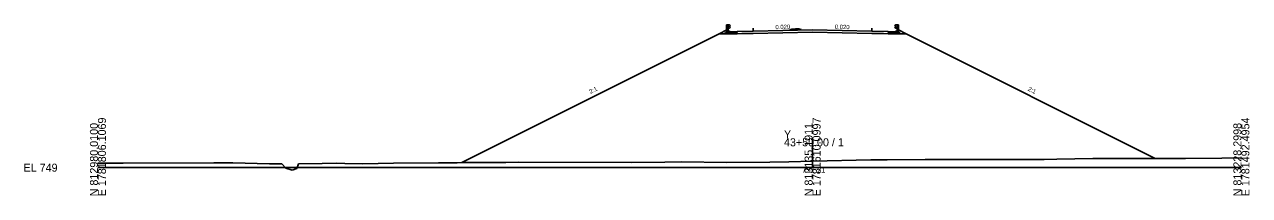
# Model space of a CAD drawing. Extents: x -12583 to 5303, y -44 to 25667.
# Drawn here: x 2874.3 to 3302.8, y 3990.3 to 4049.9 of the extents above; entities that cross this region are included whole.
import ezdxf

# ---------------------------------------------------------------- set-up
doc = ezdxf.new("R2010")
doc.units = 0
for name, color, linetype in [('Exist Cross Section Cell', 7, 'Continuous'), ('Exist XS Center Line Elevation Label', 7, 'Continuous'), ('Exist XS Ground Line', 7, 'Continuous'), ('Prop Conc 5in Monolithic Surface Mount Island', 7, 'Continuous'), ('Prop XS Dump Level', 7, 'Continuous'), ('Prop XS Earthwork Shape', 7, 'Continuous'), ('Prop XS EOT Tick Mark', 7, 'Continuous'), ('Prop XS Finish Grade', 7, 'Continuous'), ('Prop XS Finish Grade CurbGutter', 7, 'Continuous'), ('Prop XS Finish Grade Earthwork', 7, 'Continuous'), ('Prop XS Finish Grade Paved Shoulder', 7, 'Continuous'), ('Prop XS Finish Grade Pavement', 7, 'Continuous'), ('Prop XS Guardrail', 7, 'Continuous'), ('Prop XS Pvmt Edge Slope', 7, 'Continuous'), ('Prop XS SE Text', 7, 'Continuous'), ('Prop XS Side Slope Text', 7, 'Continuous'), ('Prop XS Subgrade CurbGutter', 7, 'Continuous'), ('Prop XS Subgrade Earthwork', 7, 'Continuous')]:
    doc.layers.add(name, color=color, linetype=linetype)

msp = doc.modelspace()

# ---------------------------------------------------------------- linework, layer by layer
at = {"layer": 'Exist Cross Section Cell'}
for p, q in [((3150, 4000), (3150, 4010.25)), ((2900, 4000), (3150, 4000)), ((3150, 4000), (3300, 4000))]:
    msp.add_line(p, q, dxfattribs=at)
at = {"layer": 'Exist XS Ground Line'}
for p, q in [((3150, 4002.21), (3170.43, 4002.73)), ((3170.43, 4002.73), (3176.11, 4002.68)), ((3176.11, 4002.68), (3189.37, 4002.82)), ((3189.37, 4002.82), (3202.3, 4002.89)), ((3202.3, 4002.89), (3221.1, 4002.86)), ((3221.1, 4002.86), (3230.99, 4002.9)), ((3230.99, 4002.9), (3235.46, 4002.98)), ((3235.46, 4002.98), (3248.09, 4003.22)), ((3248.09, 4003.22), (3249.41, 4003.25)), ((3249.41, 4003.25), (3251.28, 4003.24)), ((3251.28, 4003.24), (3267.82, 4003.2)), ((3267.82, 4003.2), (3280.49, 4003.16)), ((3280.49, 4003.16), (3293.13, 4003.35)), ((3293.13, 4003.35), (3300, 4003.42)), ((2900, 4001.53), (2904.75, 4001.58)), ((2904.75, 4001.58), (2908.78, 4001.58)), ((2908.78, 4001.58), (2940.5, 4001.69)), ((2940.5, 4001.69), (2943.57, 4001.65)), ((2943.57, 4001.65), (2944.72, 4001.71)), ((2944.72, 4001.71), (2947.19, 4001.66)), ((2947.19, 4001.66), (2960.04, 4001.36)), ((2960.04, 4001.36), (2964.29, 4001.39)), ((2964.29, 4001.39), (2965.68, 3999.83)), ((2965.68, 3999.83), (2968, 3999.09)), ((2968, 3999.09), (2969.55, 3999.69)), ((2969.55, 3999.69), (2970.21, 4001.28)), ((2970.21, 4001.28), (2978.42, 4001.4)), ((2978.42, 4001.4), (2983.42, 4001.6)), ((2983.42, 4001.6), (2986.42, 4001.47)), ((2986.42, 4001.47), (2992.63, 4001.31)), ((2992.63, 4001.31), (3003.37, 4001.54)), ((3003.37, 4001.54), (3019.12, 4001.68)), ((3019.12, 4001.68), (3025.68, 4001.74)), ((3025.68, 4001.74), (3042.74, 4001.83)), ((3042.74, 4001.83), (3047.13, 4001.87)), ((3047.13, 4001.87), (3086.66, 4001.83)), ((3086.66, 4001.83), (3098.26, 4001.93)), ((3098.26, 4001.93), (3104.08, 4002)), ((3104.08, 4002), (3120.01, 4001.85)), ((3120.01, 4001.85), (3135.07, 4001.9)), ((3135.07, 4001.9), (3141.68, 4002)), ((3141.68, 4002), (3150, 4002.21))]:
    msp.add_line(p, q, dxfattribs=at)
at = {"layer": 'Prop Conc 5in Monolithic Surface Mount Island'}
for p, q in [((3142, 4048.07), (3142.74, 4048.34)), ((3142, 4047.91), (3142, 4048.07)), ((3142.74, 4048.34), (3143.99, 4048.39)), ((3145.24, 4048.39), (3143.99, 4048.39)), ((3146, 4048.15), (3145.24, 4048.39)), ((3146, 4047.99), (3146, 4048.15))]:
    msp.add_line(p, q, dxfattribs=at)
at = {"layer": 'Prop XS Dump Level'}
for p, q in [((3129.25, 4047.65), (3150, 4048.07)), ((3150, 4048.07), (3170.75, 4047.65))]:
    msp.add_line(p, q, dxfattribs=at)
at = {"layer": 'Prop XS Earthwork Shape'}
msp.add_lwpolyline([(3129.25, 4046.86), (3125.25, 4046.78), (3123.58, 4046.74), (3119.19, 4046.74), (3117.32, 4046.74), (3027.33, 4001.75), (3042.74, 4001.83), (3047.13, 4001.87), (3086.66, 4001.83), (3098.26, 4001.93), (3104.08, 4002), (3120.01, 4001.85), (3135.07, 4001.9), (3141.68, 4002), (3150, 4002.21), (3170.43, 4002.73), (3176.11, 4002.68), (3189.37, 4002.82), (3202.3, 4002.89), (3221.1, 4002.86), (3230.99, 4002.9), (3235.46, 4002.98), (3248.09, 4003.22), (3249.41, 4003.25), (3251.28, 4003.24), (3267.82, 4003.2), (3269.79, 4003.19), (3182.68, 4046.74), (3180.81, 4046.74), (3176.42, 4046.74), (3174.75, 4046.78), (3170.75, 4046.86), (3150, 4047.27)], close=True, dxfattribs=at)
at = {"layer": 'Prop XS EOT Tick Mark'}
for p, q in [((3129.25, 4047.65), (3129.25, 4048.65)), ((3170.75, 4047.65), (3170.75, 4048.65))]:
    msp.add_line(p, q, dxfattribs=at)
at = {"layer": 'Prop XS Finish Grade'}
for p, q in [((3117.32, 4046.74), (3119.98, 4048.07)), ((3120.56, 4047.78), (3119.98, 4048.07)), ((3179.44, 4047.78), (3180.02, 4048.07)), ((3182.68, 4046.74), (3180.02, 4048.07))]:
    msp.add_line(p, q, dxfattribs=at)
at = {"layer": 'Prop XS Finish Grade CurbGutter'}
for p, q in [((3121.25, 4047.44), (3120.56, 4047.78)), ((3123.58, 4047.54), (3121.25, 4047.44)), ((3176.42, 4047.54), (3178.75, 4047.44)), ((3178.75, 4047.44), (3179.44, 4047.78))]:
    msp.add_line(p, q, dxfattribs=at)
at = {"layer": 'Prop XS Finish Grade Earthwork'}
for p, q in [((3117.32, 4046.74), (3027.33, 4001.75)), ((3182.68, 4046.74), (3269.79, 4003.19))]:
    msp.add_line(p, q, dxfattribs=at)
at = {"layer": 'Prop XS Finish Grade Paved Shoulder'}
for p, q in [((3129.25, 4047.65), (3123.58, 4047.54)), ((3170.75, 4047.65), (3176.42, 4047.54))]:
    msp.add_line(p, q, dxfattribs=at)
at = {"layer": 'Prop XS Finish Grade Pavement'}
for p, q in [((3129.25, 4047.65), (3150, 4048.07)), ((3150, 4048.07), (3170.75, 4047.65)), ((3150, 4048.07), (3170.75, 4047.65))]:
    msp.add_line(p, q, dxfattribs=at)
at = {"layer": 'Prop XS Guardrail'}
for p, q in [((3119.93, 4049.84), (3120.43, 4049.84)), ((3119.93, 4047.34), (3119.93, 4049.84)), ((3120.43, 4049.84), (3120.93, 4049.84)), ((3120.43, 4049.84), (3120.43, 4047.34)), ((3120.93, 4049.84), (3121.22, 4049.64)), ((3121.22, 4049.64), (3121.25, 4049.58)), ((3178.78, 4049.64), (3178.75, 4049.58)), ((3179.07, 4049.84), (3178.78, 4049.64)), ((3179.57, 4049.84), (3179.07, 4049.84)), ((3180.07, 4049.84), (3179.57, 4049.84)), ((3179.57, 4049.84), (3179.57, 4047.34)), ((3180.07, 4047.34), (3180.07, 4049.84)), ((3120.93, 4048.7), (3120.43, 4048.7)), ((3121.22, 4049.52), (3120.93, 4049.32)), ((3120.93, 4049.32), (3120.93, 4049.22)), ((3120.93, 4049.22), (3121.22, 4049.02)), ((3121.22, 4048.9), (3120.93, 4048.7)), ((3121.25, 4049.58), (3121.22, 4049.52)), ((3121.22, 4049.02), (3121.25, 4048.96)), ((3121.25, 4048.96), (3121.22, 4048.9)), ((3178.75, 4049.58), (3178.78, 4049.52)), ((3178.78, 4049.02), (3178.75, 4048.96)), ((3178.75, 4048.96), (3178.78, 4048.9)), ((3178.78, 4049.52), (3179.07, 4049.32)), ((3179.07, 4049.22), (3178.78, 4049.02)), ((3178.78, 4048.9), (3179.07, 4048.7)), ((3179.07, 4049.32), (3179.07, 4049.22)), ((3179.07, 4048.7), (3179.57, 4048.7))]:
    msp.add_line(p, q, dxfattribs=at)
at = {"layer": 'Prop XS Pvmt Edge Slope'}
for p, q in [((3119.56, 4047.12), (3119.19, 4046.74)), ((3120.56, 4047.12), (3119.56, 4047.12)), ((3179.44, 4047.12), (3180.44, 4047.12)), ((3180.44, 4047.12), (3180.81, 4046.74))]:
    msp.add_line(p, q, dxfattribs=at)
at = {"layer": 'Prop XS Subgrade CurbGutter'}
for p, q in [((3120.56, 4047.12), (3120.56, 4047.78)), ((3123.58, 4047.12), (3120.56, 4047.12)), ((3123.58, 4047.54), (3123.58, 4047.12)), ((3176.42, 4047.54), (3176.42, 4047.12)), ((3176.42, 4047.12), (3179.44, 4047.12)), ((3179.44, 4047.12), (3179.44, 4047.78))]:
    msp.add_line(p, q, dxfattribs=at)
at = {"layer": 'Prop XS Subgrade Earthwork'}
for p, q in [((3119.19, 4046.74), (3117.32, 4046.74)), ((3123.58, 4046.74), (3119.19, 4046.74)), ((3125.25, 4046.78), (3123.58, 4046.74)), ((3129.25, 4046.86), (3125.25, 4046.78)), ((3150, 4047.27), (3129.25, 4046.86)), ((3170.75, 4046.86), (3150, 4047.27)), ((3170.75, 4046.86), (3174.75, 4046.78)), ((3174.75, 4046.78), (3176.42, 4046.74)), ((3176.42, 4046.74), (3180.81, 4046.74)), ((3180.81, 4046.74), (3182.68, 4046.74))]:
    msp.add_line(p, q, dxfattribs=at)

# ---------------------------------------------------------------- texts
at = {"layer": 'Exist Cross Section Cell'}
for s, p in [('N 812980.0100', (2900, 3990)), ('E 1781806.1069', (2902.8, 3990)), ('N 813135.1911', (3150, 3990)), ('E 1781610.0997', (3152.8, 3990)), ('N 813228.2998', (3300, 3990)), ('E 1781492.4954', (3302.8, 3990))]:
    msp.add_text(s, height=2.8, rotation=90, dxfattribs=at).set_placement(p)
for s, p in [('Y', (3140, 4010.25)), ('43+50.00 / 1', (3140, 4007.45)), ('EL 749', (2874, 3998.6))]:
    msp.add_text(s, height=2.8, dxfattribs=at).set_placement(p)
at = {"layer": 'Exist XS Center Line Elevation Label'}
msp.add_text('751.21', height=2, dxfattribs=at).set_placement((3146.32, 3998.21))
at = {"layer": 'Prop XS Dump Level'}
msp.add_text('Case2', height=0.04, dxfattribs=at).set_placement((3123.58, 4047.5))
at = {"layer": 'Prop XS SE Text'}
for rotation, p in [(1.1458, (3137, 4048.31)), (358.8542, (3157.75, 4048.41)), (358.8542, (3157.75, 4048.41))]:
    msp.add_text('0.020', height=1.5, rotation=rotation, dxfattribs=at).set_placement(p)
at = {"layer": 'Prop XS Side Slope Text'}
for rotation, p in [(26.5651, (3072.32, 4025.72)), (333.4349, (3225.15, 4026.99))]:
    msp.add_text('2:1', height=1.5, rotation=rotation, dxfattribs=at).set_placement(p)

doc.saveas('drawing.dxf')
